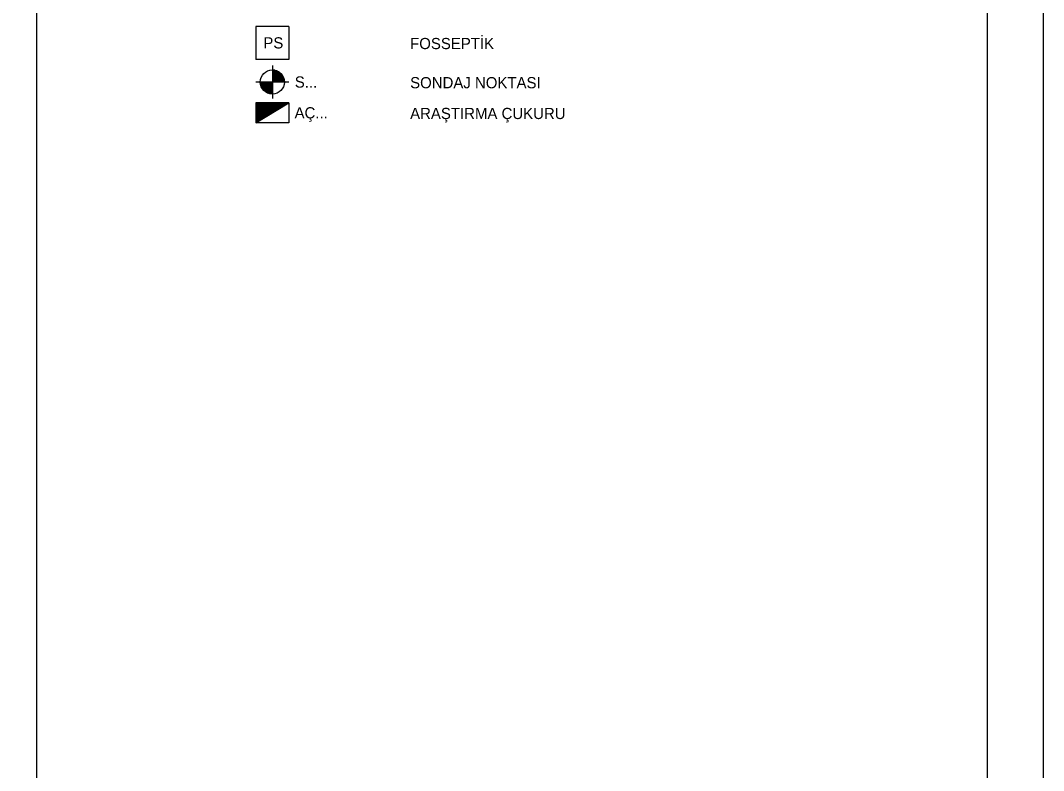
# Model space of a CAD drawing. Extents: x -10 to 1145, y -10 to 821.
# Drawn here: x 962.1 to 1145, y 551.5 to 685.6 of the extents above; entities that cross this region are included whole.
import ezdxf

# ---------------------------------------------------------------- set-up
doc = ezdxf.new("R2010")
doc.units = 0
for name, color, linetype in [('Lejand', 7, 'Continuous'), ('Level 51', 7, 'Continuous'), ('Level 52', 7, 'Continuous')]:
    doc.layers.add(name, color=color, linetype=linetype)

msp = doc.modelspace()

# ---------------------------------------------------------------- linework, layer by layer
at = {"layer": 'Lejand'}
for p, q in [((1010.09, 684.5), (1004.19, 684.5)), ((1004.19, 684.5), (1004.19, 678.6)), ((1010.09, 684.5), (1010.09, 678.6)), ((1010.09, 678.6), (1004.19, 678.6)), ((1007.14, 677.5), (1007.14, 671.6)), ((1007.24, 676.7), (1007.24, 674.55)), ((1007.34, 676.69), (1007.34, 674.55)), ((1007.61, 676.65), (1007.14, 676.65)), ((1007.93, 676.55), (1007.14, 676.55)), ((1008.15, 676.45), (1007.14, 676.45)), ((1008.32, 676.35), (1007.14, 676.35)), ((1008.46, 676.25), (1007.14, 676.25)), ((1008.58, 676.15), (1007.14, 676.15)), ((1008.68, 676.05), (1007.14, 676.05)), ((1008.77, 675.95), (1007.14, 675.95)), ((1008.86, 675.85), (1007.14, 675.85)), ((1008.93, 675.75), (1007.14, 675.75)), ((1008.99, 675.65), (1007.14, 675.65)), ((1009.05, 675.55), (1007.14, 675.55)), ((1009.1, 675.45), (1007.14, 675.45)), ((1009.14, 675.35), (1007.14, 675.35)), ((1009.18, 675.25), (1007.14, 675.25)), ((1009.21, 675.15), (1007.14, 675.15)), ((1009.23, 675.05), (1007.14, 675.05)), ((1009.26, 674.95), (1007.14, 674.95)), ((1007.44, 676.68), (1007.44, 674.55)), ((1007.54, 676.66), (1007.54, 674.55)), ((1007.64, 676.64), (1007.64, 674.55)), ((1007.74, 676.62), (1007.74, 674.55)), ((1007.84, 676.58), (1007.84, 674.55)), ((1007.94, 676.55), (1007.94, 674.55)), ((1008.04, 676.5), (1008.04, 674.55)), ((1008.14, 676.45), (1008.14, 674.55)), ((1008.24, 676.4), (1008.24, 674.55)), ((1008.34, 676.33), (1008.34, 674.55)), ((1008.44, 676.26), (1008.44, 674.55)), ((1008.54, 676.18), (1008.54, 674.55)), ((1008.64, 676.09), (1008.64, 674.55)), ((1008.74, 675.99), (1008.74, 674.55)), ((1008.84, 675.87), (1008.84, 674.55)), ((1008.94, 675.73), (1008.94, 674.55)), ((1009.04, 675.56), (1009.04, 674.55)), ((1009.14, 675.34), (1009.14, 674.55)), ((1009.24, 675.01), (1009.24, 674.55)), ((1010.09, 674.55), (1004.19, 674.55)), ((1007.14, 674.45), (1004.99, 674.45)), ((1007.14, 674.35), (1005, 674.35)), ((1007.14, 674.25), (1005.01, 674.25)), ((1007.14, 674.15), (1005.03, 674.15)), ((1005.04, 674.55), (1005.04, 674.09)), ((1007.14, 674.05), (1005.05, 674.05)), ((1007.14, 673.95), (1005.08, 673.95)), ((1007.14, 673.85), (1005.11, 673.85)), ((1005.14, 674.55), (1005.14, 673.76)), ((1007.14, 673.75), (1005.15, 673.75)), ((1007.14, 673.65), (1005.19, 673.65)), ((1005.24, 674.55), (1005.24, 673.54)), ((1007.14, 673.55), (1005.24, 673.55)), ((1007.14, 673.45), (1005.29, 673.45)), ((1005.34, 674.55), (1005.34, 673.37)), ((1007.14, 673.35), (1005.36, 673.35)), ((1007.14, 673.25), (1005.43, 673.25)), ((1005.44, 674.55), (1005.44, 673.23)), ((1007.14, 673.15), (1005.51, 673.15)), ((1005.54, 674.55), (1005.54, 673.11)), ((1007.14, 673.05), (1005.6, 673.05)), ((1005.64, 674.55), (1005.64, 673.01)), ((1005.74, 674.55), (1005.74, 672.92)), ((1005.84, 674.55), (1005.84, 672.84)), ((1005.94, 674.55), (1005.94, 672.77)), ((1006.04, 674.55), (1006.04, 672.7)), ((1006.14, 674.55), (1006.14, 672.65)), ((1006.24, 674.55), (1006.24, 672.6)), ((1006.34, 674.55), (1006.34, 672.55)), ((1006.44, 674.55), (1006.44, 672.52)), ((1006.54, 674.55), (1006.54, 672.49)), ((1006.64, 674.55), (1006.64, 672.46)), ((1006.74, 674.55), (1006.74, 672.44)), ((1006.84, 674.55), (1006.84, 672.42)), ((1006.94, 674.55), (1006.94, 672.41)), ((1007.04, 674.55), (1007.04, 672.4)), ((1009.27, 674.85), (1007.14, 674.85)), ((1009.28, 674.75), (1007.14, 674.75)), ((1009.29, 674.65), (1007.14, 674.65)), ((1007.14, 672.95), (1005.71, 672.95)), ((1007.14, 672.85), (1005.83, 672.85)), ((1007.14, 672.75), (1005.97, 672.75)), ((1007.14, 672.65), (1006.13, 672.65)), ((1007.14, 672.55), (1006.35, 672.55)), ((1007.14, 672.45), (1006.68, 672.45)), ((1010.09, 670.85), (1004.19, 670.85)), ((1004.19, 670.85), (1004.19, 667.25)), ((1004.19, 667.25), (1010.09, 670.85)), ((1009.93, 670.75), (1004.19, 670.75)), ((1009.76, 670.65), (1004.19, 670.65)), ((1009.6, 670.55), (1004.19, 670.55)), ((1009.44, 670.45), (1004.19, 670.45)), ((1009.27, 670.35), (1004.19, 670.35)), ((1009.11, 670.25), (1004.19, 670.25)), ((1008.94, 670.15), (1004.19, 670.15)), ((1008.78, 670.05), (1004.19, 670.05)), ((1008.62, 669.95), (1004.19, 669.95)), ((1008.45, 669.85), (1004.19, 669.85)), ((1008.29, 669.75), (1004.19, 669.75)), ((1008.13, 669.65), (1004.19, 669.65)), ((1007.96, 669.55), (1004.19, 669.55)), ((1007.8, 669.45), (1004.19, 669.45)), ((1004.29, 670.85), (1004.29, 667.31)), ((1004.39, 670.85), (1004.39, 667.37)), ((1004.49, 670.85), (1004.49, 667.43)), ((1004.59, 670.85), (1004.59, 667.49)), ((1004.69, 670.85), (1004.69, 667.56)), ((1004.79, 670.85), (1004.79, 667.62)), ((1004.89, 670.85), (1004.89, 667.68)), ((1004.99, 670.85), (1004.99, 667.74)), ((1005.09, 670.85), (1005.09, 667.8)), ((1005.19, 670.85), (1005.19, 667.86)), ((1005.29, 670.85), (1005.29, 667.92)), ((1005.39, 670.85), (1005.39, 667.98)), ((1005.49, 670.85), (1005.49, 668.04)), ((1005.59, 670.85), (1005.59, 668.1)), ((1005.69, 670.85), (1005.69, 668.17)), ((1005.79, 670.85), (1005.79, 668.23)), ((1005.89, 670.85), (1005.89, 668.29)), ((1005.99, 670.85), (1005.99, 668.35)), ((1006.09, 670.85), (1006.09, 668.41)), ((1006.19, 670.85), (1006.19, 668.47)), ((1006.29, 670.85), (1006.29, 668.53)), ((1006.39, 670.85), (1006.39, 668.59)), ((1006.49, 670.85), (1006.49, 668.65)), ((1006.59, 670.85), (1006.59, 668.71)), ((1006.69, 670.85), (1006.69, 668.78)), ((1006.79, 670.85), (1006.79, 668.84)), ((1006.89, 670.85), (1006.89, 668.9)), ((1006.99, 670.85), (1006.99, 668.96)), ((1007.09, 670.85), (1007.09, 669.02)), ((1007.19, 670.85), (1007.19, 669.08)), ((1007.29, 670.85), (1007.29, 669.14)), ((1007.39, 670.85), (1007.39, 669.2)), ((1007.49, 670.85), (1007.49, 669.26)), ((1007.59, 670.85), (1007.59, 669.32)), ((1007.69, 670.85), (1007.69, 669.39)), ((1007.79, 670.85), (1007.79, 669.45)), ((1007.89, 670.85), (1007.89, 669.51)), ((1007.99, 670.85), (1007.99, 669.57)), ((1008.09, 670.85), (1008.09, 669.63)), ((1008.19, 670.85), (1008.19, 669.69)), ((1008.29, 670.85), (1008.29, 669.75)), ((1008.39, 670.85), (1008.39, 669.81)), ((1008.49, 670.85), (1008.49, 669.87)), ((1008.59, 670.85), (1008.59, 669.94)), ((1008.69, 670.85), (1008.69, 670)), ((1008.79, 670.85), (1008.79, 670.06)), ((1008.89, 670.85), (1008.89, 670.12)), ((1008.99, 670.85), (1008.99, 670.18)), ((1009.09, 670.85), (1009.09, 670.24)), ((1009.19, 670.85), (1009.19, 670.3)), ((1009.29, 670.85), (1009.29, 670.36)), ((1009.39, 670.85), (1009.39, 670.42)), ((1009.49, 670.85), (1009.49, 670.48)), ((1009.59, 670.85), (1009.59, 670.55)), ((1009.69, 670.85), (1009.69, 670.61)), ((1009.79, 670.85), (1009.79, 670.67)), ((1009.89, 670.85), (1009.89, 670.73)), ((1009.99, 670.85), (1009.99, 670.79)), ((1010.09, 670.85), (1010.09, 667.25)), ((1007.63, 669.35), (1004.19, 669.35)), ((1007.47, 669.25), (1004.19, 669.25)), ((1007.31, 669.15), (1004.19, 669.15)), ((1007.14, 669.05), (1004.19, 669.05)), ((1006.98, 668.95), (1004.19, 668.95)), ((1006.81, 668.85), (1004.19, 668.85)), ((1006.65, 668.75), (1004.19, 668.75)), ((1006.49, 668.65), (1004.19, 668.65)), ((1006.32, 668.55), (1004.19, 668.55)), ((1006.16, 668.45), (1004.19, 668.45)), ((1005.99, 668.35), (1004.19, 668.35)), ((1005.83, 668.25), (1004.19, 668.25)), ((1005.67, 668.15), (1004.19, 668.15)), ((1005.5, 668.05), (1004.19, 668.05)), ((1005.34, 667.95), (1004.19, 667.95)), ((1005.18, 667.85), (1004.19, 667.85)), ((1005.01, 667.75), (1004.19, 667.75)), ((1004.85, 667.65), (1004.19, 667.65)), ((1004.68, 667.55), (1004.19, 667.55)), ((1004.52, 667.45), (1004.19, 667.45)), ((1004.36, 667.35), (1004.19, 667.35)), ((1010.09, 667.25), (1004.19, 667.25))]:
    msp.add_line(p, q, dxfattribs=at)
msp.add_circle((1007.14, 674.55), 2.15, dxfattribs=at)
at = {"layer": 'Level 51'}
msp.add_lwpolyline([(-10, -10), (1145, -10), (1145, 821), (-10, 821)], close=True, dxfattribs=at)
at = {"layer": 'Level 52'}
msp.add_lwpolyline([(965, 287), (1135, 287), (1135, 811), (965, 811)], close=True, dxfattribs=at)

# ---------------------------------------------------------------- texts
at = {"layer": 'Lejand'}
for s, p in [('PS', (1005.53, 680.55)), ('S...', (1011.15, 673.55)), ('SONDAJ NOKTASI', (1031.77, 673.43)), ('AÇ...', (1011.11, 668.05)), ('ARAŞTIRMA ÇUKURU', (1031.77, 667.93))]:
    msp.add_text(s, height=2, rotation=0.0008, dxfattribs=at).set_placement(p)
msp.add_text('FOSSEPTİK', height=2, dxfattribs=at).set_placement((1031.77, 680.43))

doc.saveas('drawing.dxf')
